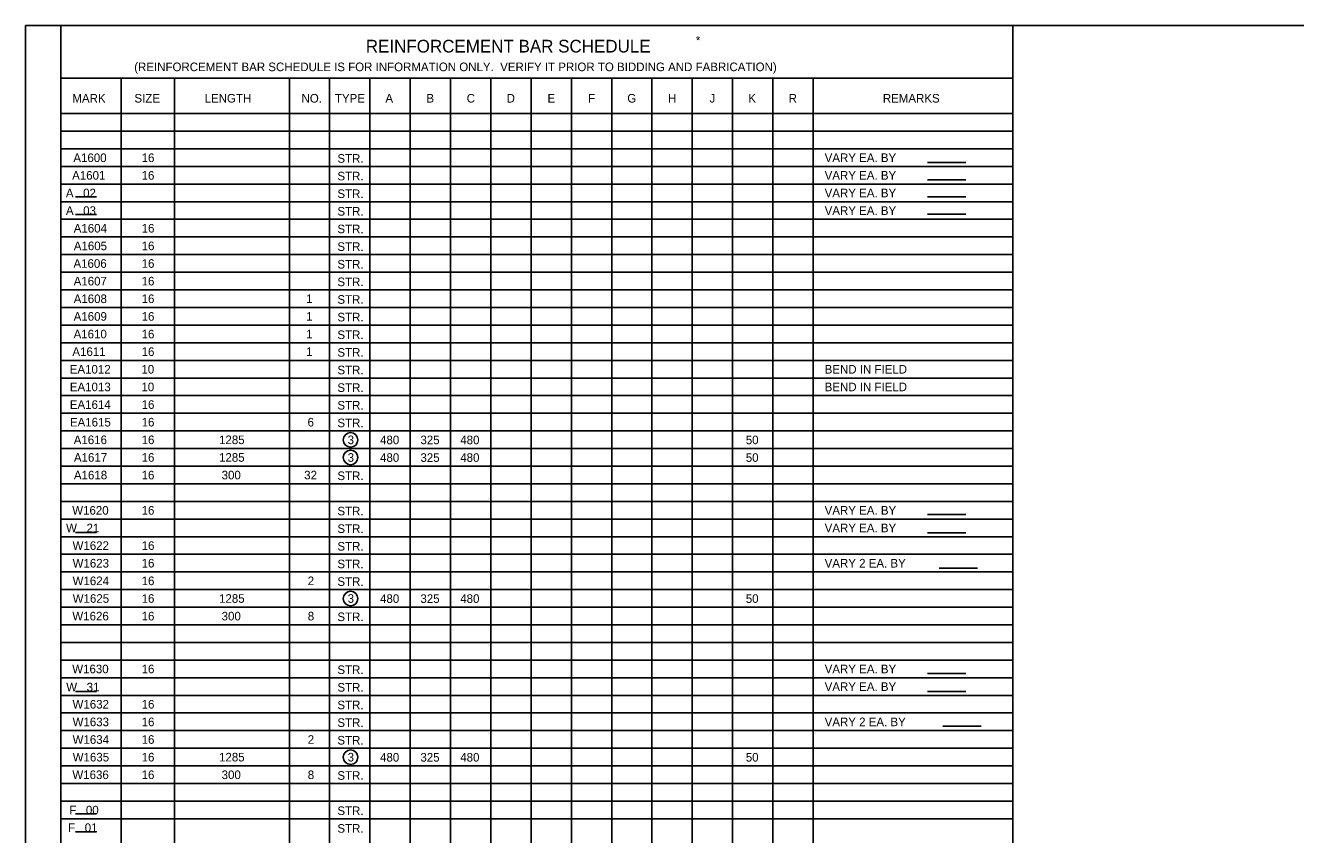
# Model space of a CAD drawing. Extents: x 638340 to 640241, y 295465 to 298435.
# Drawn here: x 639316.5 to 639759.8, y 297544.1 to 297826.5 of the extents above; entities that cross this region are included whole.
import ezdxf

# ---------------------------------------------------------------- set-up
doc = ezdxf.new("R2010")
doc.units = 0
for name, color, linetype in [('2', 7, 'Continuous'), ('4', 7, 'Continuous'), ('6', 7, 'Continuous')]:
    doc.layers.add(name, color=color, linetype=linetype)

msp = doc.modelspace()

# ---------------------------------------------------------------- linework, layer by layer
at = {"layer": '2'}
for p, q in [((639316.46, 297262.46), (639316.46, 297826.46)), ((639316.46, 297826.46), (640102.46, 297826.46))]:
    msp.add_line(p, q, dxfattribs=at)
at = {"layer": '4'}
for p, q in [((639631.3, 297778.6), (639644.67, 297778.6)), ((639631.3, 297772.6), (639644.67, 297772.6)), ((639333.9, 297766.68), (639341.31, 297766.68)), ((639631.3, 297766.6), (639644.67, 297766.6)), ((639631.3, 297760.6), (639644.67, 297760.6)), ((639333.9, 297760.49), (639341.31, 297760.49)), ((639631.3, 297655.83), (639644.67, 297655.83)), ((639333.9, 297649.48), (639341.31, 297649.48)), ((639631.3, 297649.37), (639644.67, 297649.37)), ((639635.38, 297637.1), (639648.76, 297637.1)), ((639631.3, 297600.27), (639644.67, 297600.27)), ((639333.9, 297594.03), (639341.31, 297594.03)), ((639631.3, 297594.03), (639644.67, 297594.03)), ((639636.68, 297581.97), (639650.05, 297581.97)), ((639333.9, 297551.37), (639341.31, 297551.37)), ((639333.9, 297545.11), (639341.31, 297545.11))]:
    msp.add_line(p, q, dxfattribs=at)
for centre in [(639429.95, 297681.84), (639429.95, 297675.69), (639429.95, 297626.47), (639429.95, 297571.11)]:
    msp.add_circle(centre, 2.55, dxfattribs=at)
at = {"layer": '6'}
for p, q in [((639328.8, 297826.46), (639661.06, 297826.46)), ((639328.8, 297408.13), (639328.8, 297826.46)), ((639661.06, 297356.79), (639661.06, 297826.46)), ((639328.8, 297808), (639661.06, 297808)), ((639349.89, 297795.7), (639349.89, 297808)), ((639368.45, 297795.7), (639368.45, 297808)), ((639408.58, 297795.7), (639408.58, 297808)), ((639422.64, 297795.7), (639422.64, 297808)), ((639436.7, 297795.7), (639436.7, 297808)), ((639450.76, 297795.7), (639450.76, 297808)), ((639464.82, 297795.7), (639464.82, 297808)), ((639478.89, 297795.7), (639478.89, 297808)), ((639492.95, 297795.7), (639492.95, 297808)), ((639507.01, 297795.7), (639507.01, 297808)), ((639521.07, 297795.7), (639521.07, 297808)), ((639535.13, 297795.7), (639535.13, 297808)), ((639549.19, 297795.7), (639549.19, 297808)), ((639563.25, 297795.7), (639563.25, 297808)), ((639577.32, 297795.7), (639577.32, 297808)), ((639591.38, 297795.7), (639591.38, 297808)), ((639328.8, 297795.7), (639661.06, 297795.7)), ((639349.89, 297408.13), (639349.89, 297795.7)), ((639368.45, 297408.13), (639368.45, 297795.7)), ((639408.58, 297408.13), (639408.58, 297795.7)), ((639422.64, 297408.13), (639422.64, 297795.7)), ((639436.7, 297408.13), (639436.7, 297795.7)), ((639450.76, 297408.13), (639450.76, 297795.7)), ((639464.82, 297408.13), (639464.82, 297795.7)), ((639478.89, 297408.13), (639478.89, 297795.7)), ((639492.95, 297408.13), (639492.95, 297795.7)), ((639507.01, 297408.13), (639507.01, 297795.7)), ((639521.07, 297408.13), (639521.07, 297795.7)), ((639535.13, 297408.13), (639535.13, 297795.7)), ((639549.19, 297408.13), (639549.19, 297795.7)), ((639563.25, 297408.13), (639563.25, 297795.7)), ((639577.32, 297408.13), (639577.32, 297795.7)), ((639591.38, 297408.13), (639591.38, 297795.7)), ((639328.8, 297789.54), (639661.06, 297789.54)), ((639328.8, 297783.39), (639661.06, 297783.39)), ((639328.8, 297777.24), (639661.06, 297777.24)), ((639328.8, 297771.09), (639661.06, 297771.09)), ((639328.8, 297764.94), (639661.06, 297764.94)), ((639328.8, 297758.79), (639661.06, 297758.79)), ((639328.8, 297752.63), (639661.06, 297752.63)), ((639328.8, 297746.48), (639661.06, 297746.48)), ((639328.8, 297740.33), (639661.06, 297740.33)), ((639328.8, 297734.18), (639661.06, 297734.18)), ((639328.8, 297728.03), (639661.06, 297728.03)), ((639328.8, 297721.87), (639661.06, 297721.87)), ((639328.8, 297715.72), (639661.06, 297715.72)), ((639328.8, 297709.57), (639661.06, 297709.57)), ((639328.8, 297703.42), (639661.06, 297703.42)), ((639328.8, 297697.27), (639661.06, 297697.27)), ((639328.8, 297691.11), (639661.06, 297691.11)), ((639328.8, 297684.96), (639661.06, 297684.96)), ((639328.8, 297678.81), (639661.06, 297678.81)), ((639328.8, 297672.66), (639661.06, 297672.66)), ((639328.8, 297666.51), (639661.06, 297666.51)), ((639328.8, 297660.36), (639661.06, 297660.36)), ((639328.8, 297654.2), (639661.06, 297654.2)), ((639328.8, 297648.05), (639661.06, 297648.05)), ((639328.8, 297641.9), (639661.06, 297641.9)), ((639328.8, 297635.75), (639661.06, 297635.75)), ((639328.8, 297629.6), (639661.06, 297629.6)), ((639328.8, 297623.44), (639661.06, 297623.44)), ((639328.8, 297617.29), (639661.06, 297617.29)), ((639328.8, 297611.14), (639661.06, 297611.14)), ((639328.8, 297604.99), (639661.06, 297604.99)), ((639328.8, 297598.84), (639661.06, 297598.84)), ((639328.8, 297592.68), (639661.06, 297592.68)), ((639328.8, 297586.53), (639661.06, 297586.53)), ((639328.8, 297580.38), (639661.06, 297580.38)), ((639328.8, 297574.23), (639661.06, 297574.23)), ((639328.8, 297568.08), (639661.06, 297568.08)), ((639328.8, 297561.93), (639661.06, 297561.93)), ((639328.8, 297555.77), (639661.06, 297555.77)), ((639328.8, 297549.62), (639661.06, 297549.62))]:
    msp.add_line(p, q, dxfattribs=at)

# ---------------------------------------------------------------- texts
at = {"layer": '4'}
for s, height, p in [('*', 3, (639550.45, 297819.77)), ('REINFORCEMENT BAR SCHEDULE', 4.4294, (639435.26, 297817)), ('(REINFORCEMENT BAR SCHEDULE IS FOR INFORMATION ONLY.  VERIFY IT PRIOR TO BIDDING AND FABRICATION)', 3.0001, (639354.43, 297810.49)), ('MARK', 3, (639332.85, 297799.53)), ('SIZE', 3, (639354.52, 297799.53)), ('LENGTH', 3, (639379, 297799.53)), ('NO.', 3, (639412.83, 297799.53)), ('TYPE', 3, (639424.47, 297799.53)), ('A', 3, (639442.1, 297799.53)), ('B', 3, (639456.42, 297799.53)), ('C', 3, (639470.47, 297799.53)), ('D', 3, (639484.42, 297799.53)), ('E', 3, (639498.67, 297799.53)), ('F', 3, (639512.84, 297799.53)), ('G', 3, (639526.51, 297799.53)), ('H', 3, (639540.69, 297799.53)), ('J', 3, (639555.22, 297799.53)), ('K', 3, (639568.75, 297799.53)), ('R', 3, (639582.83, 297799.53)), ('REMARKS', 3, (639615.71, 297799.53)), ('A1600', 3, (639333.19, 297778.78)), ('16', 3, (639357.02, 297778.78)), ('STR.', 3, (639425.35, 297778.53)), ('VARY EA. BY     ', 3.0001, (639595.4, 297778.78)), ('A1601', 3, (639332.77, 297772.63)), ('16', 3, (639357.02, 297772.63)), ('STR.', 3, (639425.35, 297772.38)), ('VARY EA. BY     ', 3.0001, (639595.4, 297772.63)), ('A   02', 3, (639330.58, 297766.48)), ('VARY EA. BY     ', 3.0001, (639595.4, 297766.48)), ('STR.', 3, (639425.35, 297766.23)), ('A   03', 3, (639330.6, 297760.33)), ('STR.', 3, (639425.35, 297760.08)), ('VARY EA. BY     ', 3.0001, (639595.4, 297760.33)), ('A1604', 3, (639333.32, 297754.17)), ('16', 3, (639357.02, 297754.17)), ('STR.', 3, (639425.35, 297753.93)), ('A1605', 3, (639333.35, 297748.02)), ('16', 3, (639357.02, 297748.02)), ('STR.', 3, (639425.35, 297747.78)), ('A1606', 3, (639333.23, 297741.87)), ('16', 3, (639357.02, 297741.87)), ('STR.', 3, (639425.35, 297741.62)), ('A1607', 3, (639333.3, 297735.72)), ('16', 3, (639357.02, 297735.72)), ('STR.', 3, (639425.35, 297735.47)), ('A1608', 3, (639333.31, 297729.57)), ('16', 3, (639357.02, 297729.57)), ('1', 3, (639414.46, 297729.57)), ('STR.', 3, (639425.35, 297729.32)), ('A1609', 3, (639333.3, 297723.41)), ('16', 3, (639357.02, 297723.41)), ('1', 3, (639414.46, 297723.41)), ('STR.', 3, (639425.35, 297723.17)), ('A1610', 3, (639333.27, 297717.26)), ('16', 3, (639357.02, 297717.26)), ('1', 3, (639414.46, 297717.26)), ('STR.', 3, (639425.35, 297717.02)), ('A1611', 3, (639332.85, 297711.11)), ('16', 3, (639357.02, 297711.11)), ('1', 3, (639414.46, 297711.11)), ('STR.', 3, (639425.35, 297710.86)), ('EA1012', 3, (639331.94, 297704.96)), ('10', 3, (639356.94, 297704.96)), ('STR.', 3, (639425.35, 297704.71)), ('BEND IN FIELD', 3.0001, (639595.4, 297704.96)), ('EA1013', 3, (639331.96, 297698.81)), ('10', 3, (639356.94, 297698.81)), ('STR.', 3, (639425.35, 297698.56)), ('BEND IN FIELD', 3.0001, (639595.4, 297698.81)), ('EA1614', 3, (639331.96, 297692.65)), ('16', 3, (639357.02, 297692.65)), ('STR.', 3, (639425.35, 297692.41)), ('EA1615', 3, (639331.99, 297686.5)), ('16', 3, (639357.02, 297686.5)), ('6', 3, (639414.93, 297686.5)), ('STR.', 3, (639425.35, 297686.26)), ('A1616', 3, (639333.32, 297680.35)), ('16', 3, (639357.02, 297680.35)), ('1285', 3, (639384.04, 297680.35)), ('3', 3, (639428.92, 297680.34)), ('480', 3, (639440.24, 297680.31)), ('325', 3, (639454.32, 297680.31)), ('480', 3, (639468.22, 297680.31)), ('50', 3, (639567.87, 297680.31)), ('A1617', 3, (639333.39, 297674.2)), ('16', 3, (639357.02, 297674.2)), ('1285', 3, (639384.04, 297674.2)), ('3', 3, (639428.92, 297674.19)), ('480', 3, (639440.24, 297674.16)), ('325', 3, (639454.32, 297674.16)), ('480', 3, (639468.22, 297674.16)), ('50', 3, (639567.87, 297674.16)), ('A1618', 3, (639333.39, 297668.05)), ('16', 3, (639357.02, 297668.05)), ('300', 3, (639384.94, 297668.05)), ('32', 3, (639413.76, 297668.05)), ('STR.', 3, (639425.35, 297667.8)), ('W1620', 3, (639332.8, 297655.74)), ('16', 3, (639357.02, 297655.74)), ('VARY EA. BY     ', 3.0001, (639595.4, 297655.74)), ('STR.', 3, (639425.35, 297655.5)), ('W   21', 3, (639330.66, 297649.59)), ('STR.', 3, (639425.35, 297649.35)), ('VARY EA. BY     ', 3.0001, (639595.4, 297649.59)), ('W1622', 3, (639332.91, 297643.44)), ('16', 3, (639357.02, 297643.44)), ('STR.', 3, (639425.35, 297643.19)), ('W1623', 3, (639332.93, 297637.29)), ('16', 3, (639357.02, 297637.29)), ('STR.', 3, (639425.35, 297637.04)), ('VARY 2 EA. BY     ', 3.0001, (639595.4, 297637.29)), ('W1624', 3, (639332.93, 297631.14)), ('16', 3, (639357.02, 297631.14)), ('2', 3, (639414.99, 297631.14)), ('STR.', 3, (639425.35, 297630.89)), ('W1625', 3, (639332.96, 297624.98)), ('16', 3, (639357.02, 297624.98)), ('1285', 3, (639384.04, 297624.98)), ('3', 3, (639428.92, 297624.97)), ('480', 3, (639440.24, 297624.94)), ('325', 3, (639454.32, 297624.94)), ('480', 3, (639468.22, 297624.94)), ('50', 3, (639567.87, 297624.94)), ('W1626', 3, (639332.85, 297618.83)), ('16', 3, (639357.02, 297618.83)), ('300', 3, (639384.94, 297618.83)), ('8', 3, (639415, 297618.83)), ('STR.', 3, (639425.35, 297618.59)), ('W1630', 3, (639332.8, 297600.38)), ('16', 3, (639357.02, 297600.38)), ('STR.', 3, (639425.35, 297600.13)), ('VARY EA. BY     ', 3.0001, (639595.4, 297600.38)), ('W   31', 3, (639330.71, 297594.08)), ('STR.', 3, (639425.35, 297593.98)), ('VARY EA. BY     ', 3.0001, (639595.4, 297594.22)), ('W1632', 3, (639332.91, 297588.07)), ('16', 3, (639357.02, 297588.07)), ('STR.', 3, (639425.35, 297587.83)), ('W1633', 3, (639332.93, 297581.92)), ('16', 3, (639357.02, 297581.92)), ('STR.', 3, (639425.35, 297581.67)), ('VARY 2 EA. BY     ', 3.0001, (639595.4, 297581.92)), ('W1634', 3, (639332.93, 297575.77)), ('16', 3, (639357.02, 297575.77)), ('2', 3, (639414.99, 297575.77)), ('STR.', 3, (639425.35, 297575.52)), ('W1635', 3, (639332.96, 297569.62)), ('16', 3, (639357.02, 297569.62)), ('1285', 3, (639384.04, 297569.62)), ('3', 3, (639428.92, 297569.61)), ('480', 3, (639440.24, 297569.57)), ('325', 3, (639454.32, 297569.57)), ('480', 3, (639468.22, 297569.57)), ('50', 3, (639567.87, 297569.57)), ('W1636', 3, (639332.85, 297563.47)), ('16', 3, (639357.02, 297563.47)), ('300', 3, (639384.94, 297563.47)), ('8', 3, (639415, 297563.47)), ('STR.', 3, (639425.35, 297563.22)), ('F   00', 3, (639331.78, 297551.16)), ('STR.', 3, (639425.35, 297550.92)), ('F   01', 3, (639331.36, 297545.01)), ('STR.', 3, (639425.35, 297544.76))]:
    msp.add_text(s, height=height, dxfattribs=at).set_placement(p)

doc.saveas('drawing.dxf')
